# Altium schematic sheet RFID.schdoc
size 297 x 209 mm; Symbol: Drawing-Symbol_A4; @Project Name: Hưhwwuey; @Page Count: 10; @Update Date: 2026-10-23; @Create Date: 2026-10-23; @Schematic Name: Schematic1; @Page No: 10; @Page Name: P1; Company: EasyEDA.com; Version: V1.0; Page Size: A4; Device: Drawing-Symbol_A4; @Create Time: 15:50:34; @Update Time: 15:50:34; Border: 1; Width: 1170; Height: 825; Region Start: 1; X Region Count: 6; Y Region Count: 4; Blade Width: 10; Title Block Position: 3; @Board Name: Board1
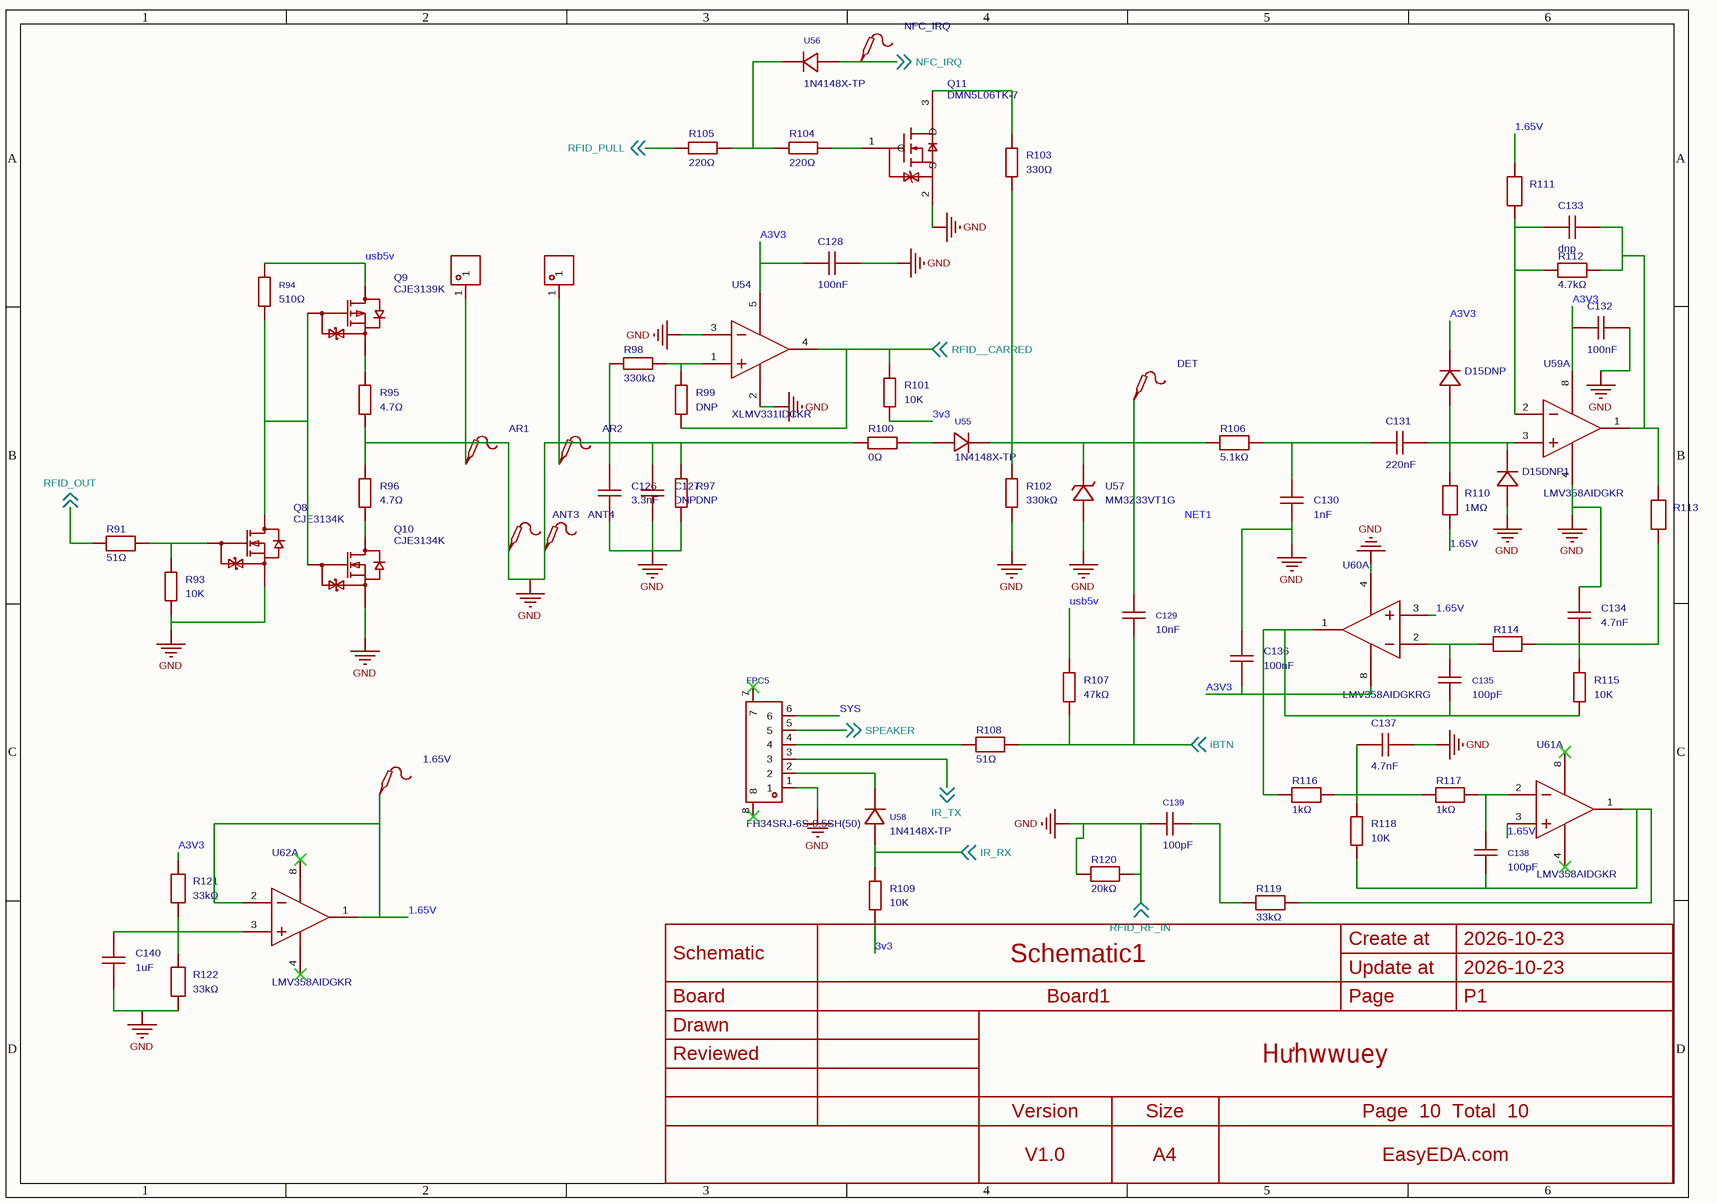
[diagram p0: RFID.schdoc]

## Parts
C126  3.3nF  [C0805]
C127  DNP  [C0402]
C128  100nF  [C0402]
C129  10nF  [C0402]
C130  1nF  [C0402]
C131  220nF  [C1206]
C132  100nF  [C0402]
C133  dnp  [C0402]
C134  4.7nF  [C0402]
C135  100pF  [C0402]
C136  100nF  [C0402]
C137  4.7nF  [C0402]
C138  100pF  [C0402]
C139  100pF  [C0402]
C140  1uF  [C0402]
CN6  YTC1P-3515-M20  [CONN-SMD_YTC1P-3515-M20]  (value not drawn)
CN7  YTC1P-3515-M20  [CONN-SMD_YTC1P-3515-M20]  (value not drawn)
D15DNP  (no value)  [DO-41_BD2.4-L4.7-P8.70-D0.9-RD]
D15DNP1  (no value)  [DO-41_BD2.4-L4.7-P8.70-D0.9-RD]
FPC5  FH34SRJ-6S-0.5SH(50)  [FFC-SMD_6P-P0.50_FH34SRJ-6S-0.5SH]
Q8  CJE3134K  [SOT-523-3_L1.6-W0.8-P1.00-LS1.6-BR]
Q9  CJE3139K  [SC-75-3_L1.6-W0.8-P1.00-LS1.7-BR]
Q10  CJE3134K  [SOT-523-3_L1.6-W0.8-P1.00-LS1.6-BR]
Q11  DMN5L06TK-7  [SOT-523-3_L1.6-W0.8-P1.00-LS1.6-BR]
R91  51Ω  [R0402]
R93  10K  [R0402]
R94  510Ω  [R0402]
R95  4.7Ω  [R0402]
R96  4.7Ω  [R0402]
R97  DNP  [R0402]
R98  330kΩ  [R0402]
R99  DNP  [R0402]
R100  0Ω  [R0402]
R101  10K  [R0402]
R102  330kΩ  [R0402]
R103  330Ω  [R0402]
R104  220Ω  [R0402]
R105  220Ω  [R0402]
R106  5.1kΩ  [R0402]
R107  47kΩ  [R0402]
R108  51Ω  [R0402]
R109  10K  [R0402]
R110  1MΩ  [R0402]
R111  (no value)  [R0402]
R112  4.7kΩ  [R0402]
R113  (no value)  [R0402]
R114  (no value)  [R0402]
R115  10K  [R0402]
R116  1kΩ  [R0402]
R117  1kΩ  [R0402]
R118  10K  [R0402]
R119  33kΩ  [R0402]
R120  20kΩ  [R0402]
R121  33kΩ  [R0402]
R122  33kΩ  [R0402]
TP58  AR1  [Test-Point-0.5mm]
TP59  ANT3  [Test-Point-0.5mm]
TP60  ANT4  [Test-Point-0.5mm]
TP61  AR2  [Test-Point-0.5mm]
TP62  NFC_IRQ  [Test-Point-0.5mm]
TP63  DET  [Test-Point-0.5mm]
TP64  1.65V  [Test-Point-0.5mm]
U54  XLMV331IDCKR  [SC-70-5_L2.1-W1.3-P0.65-LS2.1-BR]
U55  1N4148X-TP  [SOD-523F_L1.2-W0.8-LS1.7-RD]
U56  1N4148X-TP  [SOD-523F_L1.2-W0.8-LS1.7-RD]
U57  MM3Z33VT1G  [SOD-323_L1.7-W1.3-LS2.5-RD]
U58  1N4148X-TP  [SOD-523F_L1.2-W0.8-LS1.7-RD]
U59  LMV358AIDGKR  [VSSOP-8_L3.0-W3.0-P0.65-LS5.0-BL]  (part A of 2)
U60  LMV358AIDGKRG  [MSOP-8_L3.0-W3.0-P0.65-LS4.9-BL]  (part A of 2)
U61  LMV358AIDGKR  [VSSOP-8_L3.0-W3.0-P0.65-LS5.0-BL]  (part A of 2)
U62  LMV358AIDGKR  [VSSOP-8_L3.0-W3.0-P0.65-LS5.0-BL]  (part A of 2)

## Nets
GND: C126.1 C126.2 C127.1 C127.2 C128.1 C130.1 C132.1 C134.2 C136.1 C137.1 C139.2 C140.1 CN6.1 CN7.1 D15DNP1.2(A) FPC5.1 Q8.2(S) Q10.2(S) Q11.2(S) R93.1 R95.1 R96.2 R97.1 R97.2 R98.1 R100.1 R102.1 R120.1 R120.2 R122.1 TP58.1 TP59.1 TP60.1 TP61.1 U54.2(V-) U54.3(-IN) U57.2(A) U59.4(V-) U60.4(V-) ; off-sheet RFID_RF_IN  [also labelled RFID_RF_IN]
1.65V: R110.1 R111.2 TP64.1 U60.3(+IN_A) U61.3(+INA) U62.1(OUTA) U62.2(-INA)
3v3: R101.1 R109.1
A3V3: C128.2 C132.2 C136.2 D15DNP.1(K) R121.2 U54.5(V+) U59.8(V+) U60.8(V+)
iBTN: C129.1 R107.1 R108.2 ; off-sheet iBTN
IR_RX: R109.2 U58.2(A) ; off-sheet IR_RX
IR_TX: FPC5.3 ; off-sheet IR_TX
NFC_IRQ: TP62.1 U56.2(A) ; off-sheet NFC_IRQ
RFID__CARRED: R99.1 R101.2 U54.4(OUT) ; off-sheet RFID__CARRED
RFID_OUT: R91.1 ; off-sheet RFID_OUT
RFID_PULL: R105.1 ; off-sheet RFID_PULL
SPEAKER: FPC5.5 ; off-sheet SPEAKER
SYS: FPC5.6
usb5v: Q9.3(D) R94.2 R107.2
NetC129_2: C129.2 R102.2 R103.1 R106.1 TP63.1 U55.1(C) U57.1(C)
NetC130_2: C130.2 C131.1 R106.2
NetC131_2: C131.2 D15DNP.2(A) D15DNP1.1(K) R110.2 U59.3(+INA)
NetC133_1: C133.1 R112.2 R113.2 U59.1(OUTA)
NetC133_2: C133.2 R111.1 R112.1 U59.2(-INA)
NetC134_1: C134.1 R113.1 R114.1 R115.2
NetC135_1: C135.1 R115.1 R116.1 U60.1(OUT_A)
NetC135_2: C135.2 R114.2 U60.2(-IN_A)
NetC137_2: C137.2 R116.2 R117.1 R118.2
NetC138_1: C138.1 R118.1 R119.2 U61.1(OUTA)
NetC138_2: C138.2 R117.2 U61.2(-INA)
NetC139_1: C139.1 R119.1
NetC140_2: C140.2 R121.1 R122.2 U62.3(+INA)
NetFPC5_2: FPC5.2 U58.1(C)
NetFPC5_4: FPC5.4 R108.1
NetQ8_1: Q8.1(G) R91.2 R93.2
NetQ8_3: Q8.3(D) Q9.1(G) Q10.1(G) R94.1
NetQ9_2: Q9.2(S) R95.2
NetQ10_3: Q10.3(D) R96.1
NetQ11_1: Q11.1(G) R104.2
NetQ11_3: Q11.3(D) R103.2
NetR98_2: R98.2 R99.2 U54.1(+IN)
NetR100_2: R100.2 U55.2(A)
NetR104_1: R104.1 R105.2 U56.1(C)

Not connected (* = marked no-connect by the designer): FPC5 7* 8*; U61 4(V-)* 8(V+)*; U62 4(V-)* 8(V+)*

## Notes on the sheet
- Labels drawn without touching a wire or pin: NET1

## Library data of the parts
C126 = 0805N332J101CT: Capacitance:3.3nF Tolerance:±5% Tolerance:±5% Voltage Rating:100V Temperature Coefficient:NP0; Manufacturer: Walsin(华新科); AddInBom: yes; ModelId: 8c88e81f49c6409b980720ec8953afb60819f05c4eef4c71ace90d822a990e87; ModelName: C0805_L2.0-W1.3-H1.3; ModelTransform: 78.74,51.181,0,0,0,0,0,0.0005,0; Tolerance: ±5%; Voltage Rating: 100V; Temperature Coefficient: NP0
C127 C133 = CAP_0402: Symbol: CAP_OLD; 3D Model: b7d13df3e9464d7a99d0651d1a5b4d570819f05c4eef4c71ace90d822a990e87; 3D Model Transform: 39.37,19.685,0,0,0,0,0,0,0; Add into BOM: no; ConvertToPcb: yes; ModelName: C0402_L1.0-W0.5-H0.5
C128 C132 C136 = CAP_0402: Symbol: CAP_OLD; 3D Model: b7d13df3e9464d7a99d0651d1a5b4d570819f05c4eef4c71ace90d822a990e87; 3D Model Transform: 39.37,19.685,0,0,0,0,0,0,0; ConvertToPcb: yes; ModelName: C0402_L1.0-W0.5-H0.5
C129 = CC0402KRX7R9BB103: Capacitance:10nF Tolerance:±10% Tolerance:±10% Voltage Rating:50V Temperature Coefficient:X7R; Manufacturer: YAGEO(国巨); 3D Model: b7d13df3e9464d7a99d0651d1a5b4d570819f05c4eef4c71ace90d822a990e87; 3D Model Transform: 39.37,19.685,0,0,0,0,0,0,0; Tolerance: ±10%; Voltage Rating: 50V; Temperature Coefficient: X7R; AddInBom: yes; ModelName: C0402_L1.0-W0.5-H0.5
C130 = 0402CG102J500NT: Capacitance:1nF Tolerance:±5% Tolerance:±5% Voltage Rating:50V Temperature Coefficient:C0G; Manufacturer: FH(风华); AddInBom: yes; ModelId: b7d13df3e9464d7a99d0651d1a5b4d570819f05c4eef4c71ace90d822a990e87; ModelName: C0402_L1.0-W0.5-H0.5; ModelTransform: 39.37,19.685,0,0,0,0,0,0,0; Tolerance: ±5%; Voltage Rating: 50V; Temperature Coefficient: C0G
C131 = 1206B224K500CT: Capacitance:220nF Tolerance:±10% Tolerance:±10% Voltage Rating:50V Temperature Coefficient:X7R; Manufacturer: Walsin(华新科); AddInBom: yes; ModelId: c6790e9475e1483991d2c64340b24e960819f05c4eef4c71ace90d822a990e87; ModelName: C1206_L3.2-W1.6-H1.3; ModelTransform: 125.984,62.992,0,0,0,0,0,0,0; Tolerance: ±10%; Voltage Rating: 50V; Temperature Coefficient: X7R
C134 C137 = 0402B472J500CT: Capacitance:4.7nF Tolerance:±5% Tolerance:±5% Voltage Rating:50V Temperature Coefficient:X7R; Manufacturer: Walsin(华新科); AddInBom: yes; ModelId: b7d13df3e9464d7a99d0651d1a5b4d570819f05c4eef4c71ace90d822a990e87; ModelName: C0402_L1.0-W0.5-H0.5; ModelTransform: 39.37,19.685,0,0,0,0,0,0,0; Tolerance: ±5%; Voltage Rating: 50V; Temperature Coefficient: X7R
C135 C138 C139 = CC0402JRNPO9BN101: Capacitance:100pF Tolerance:±5% Tolerance:±5% Voltage Rating:50V Temperature Coefficient:NP0; Manufacturer: YAGEO(国巨); AddInBom: yes; ModelId: b7d13df3e9464d7a99d0651d1a5b4d570819f05c4eef4c71ace90d822a990e87; ModelName: C0402_L1.0-W0.5-H0.5; ModelTransform: 39.37,19.685,0,0,0,0,0,0,0; Tolerance: ±5%; Voltage Rating: 50V; Temperature Coefficient: NP0
C140 = 0402X105K160CT: Capacitance:1uF Tolerance:±10% Tolerance:±10% Voltage Rating:16V Temperature Coefficient:X5R; Manufacturer: Walsin(华新科); AddInBom: yes; ModelId: b7d13df3e9464d7a99d0651d1a5b4d570819f05c4eef4c71ace90d822a990e87; ModelName: C0402_L1.0-W0.5-H0.5; ModelTransform: 39.37,19.685,0,0,0,0,0,0,0; Tolerance: ±10%; Voltage Rating: 16V; Temperature Coefficient: X5R
CN6 CN7 = YTC1P-3515-M20: Type:Pogo Pin Number of Pins:1P Overall Length/Height:4mm Contact Material:Brass Contact Plating:Gold; Manufacturer: YIYUAN(怡远); 3D Model: e956e29c821d4094900f1c4d8f713bf40819f05c4eef4c71ace90d822a990e87; 3D Model Transform: 78.624,78.682,0,0,0,0,0,0,0; Overall Length/Height: 4mm; AddInBom: yes
D15DNP D15DNP1 = 1N4007: Symbol: D_1N4007; Add into BOM: no; ConvertToPcb: yes; ModelId: 39d8e4572d564e62a86d2224fc908dd80819f05c4eef4c71ace90d822a990e87; ModelName: DO-41_D2.4-L4.7-P8.70; ModelTransform: 374.016,94.488,0,0,0,0,0,0,-137.795
FPC5 = FH34SRJ-6S-0.5SH(50): Locking Feature:Flip-top (front insert,rear flip) Contact Type:Double-Sided Contacts, Top and Bottom Entry Number of Contacts:6P Pitch:0.5mm Mounting Type:Surface Mount, Right Angle FFC, FCB Thickness:0.3mm FFC, FCB Thickness:0.3mm Height Above Board:1mm; Manufacturer: HRS(广濑); AddInBom: yes; ModelId: 1b1aec8cff634776880d16aaa310328b0819f05c4eef4c71ace90d822a990e87; ModelName: FFC-SMD_P0.50-WS-6P; ModelTransform: 196.85,125.984,0,0,0,0,0,0.002,0; Number of Contacts: 6P; Pitch: 0.5mm; FFC, FCB Thickness: 0.3mm; Rated Voltage (Max): 50V; Current Rating (Max): 500mA; FPC/FFC Lock: Without buckle; Forward Foot / Back Foot: No polarity
Q8 Q10 = CJE3134K: Number:1 N-channel Drain to Source Voltage:20V Current - Continuous Drain(Id):750mA RDS(on):380mΩ@4.5V Pd - Power Dissipation:150mW Gate Threshold Voltage (Vgs(th)):350mV Gate Charge(Qg):- Input Capacitance(Ciss):120pF Reverse Transfer Capacitance (Crss@V; Manufacturer: CJ(江苏长电/长晶); AddInBom: yes; ModelId: 1cc59aa5ffe4420193f3c1f87584e8b70819f05c4eef4c71ace90d822a990e87; ModelName: SOT-523-3P_L1.6-W0.8-H0.9-LS1.6-P0.50; ModelTransform: 63.48633,62.992,0,180,0,0,0,0,0; Drain to Source Voltage: 20V; Current - Continuous Drain(Id): 750mA; Pd - Power Dissipation: 150mW; Gate Threshold Voltage (Vgs(th)): 350mV; Input Capacitance(Ciss): 120pF; Reverse Transfer Capacitance (Crss@Vds): 15pF; Output Capacitance(Coss): 20pF; Vgs: ±12V
Q9 = CJE3139K: Number:1 P-Channel Drain to Source Voltage:20V Current - Continuous Drain(Id):660mA RDS(on):520mΩ@4.5V Pd - Power Dissipation:150mW Gate Threshold Voltage (Vgs(th)):350mV Gate Charge(Qg):- Input Capacitance(Ciss):170pF Reverse Transfer Capacitance (Crss@V; Manufacturer: CJ(江苏长电/长晶); AddInBom: yes; ModelId: f2b5cdcfb1524051bb2c314de36aeac10819f05c4eef4c71ace90d822a990e87; ModelName: SC-75-3_L1.6-W0.8-H0.9-LS1.6-P1.0; ModelTransform: 63.48633,62.992,0,180,0,0,0,0.005,0; Drain to Source Voltage: 20V; Current - Continuous Drain(Id): 660mA; Pd - Power Dissipation: 150mW; Gate Threshold Voltage (Vgs(th)): 350mV; Input Capacitance(Ciss): 170pF; Reverse Transfer Capacitance (Crss@Vds): 15pF; Vgs: ±12V
Q11 = DMN5L06TK-7: Number:1 N-channel Drain to Source Voltage:50V Current - Continuous Drain(Id):280mA RDS(on):2.5Ω@2.5V Pd - Power Dissipation:150mW Gate Threshold Voltage (Vgs(th)):3V Gate Charge(Qg):- Input Capacitance(Ciss):50pF Reverse Transfer Capacitance (Crss@Vds):5; Manufacturer: DIODES(美台); AddInBom: yes; ModelId: 1cc59aa5ffe4420193f3c1f87584e8b70819f05c4eef4c71ace90d822a990e87; ModelName: SOT-523-3P_L1.6-W0.8-H0.9-LS1.6-P0.50; ModelTransform: 63.48633,62.992,0,180,0,0,0,0,0; Drain to Source Voltage: 50V; Current - Continuous Drain(Id): 280mA; Pd - Power Dissipation: 150mW; Gate Threshold Voltage (Vgs(th)): 3V; Input Capacitance(Ciss): 50pF; Reverse Transfer Capacitance (Crss@Vds): 5pF; Output Capacitance(Coss): 25pF; Vgs: ±20V
R91 R108 = WR04X510JTL_C384323: Type:Thick Film Resistors Resistance: Tolerance:±5% Tolerance:±5% Power(Watts): Overload Voltage (Max): Temperature Coefficient:±100ppm/℃ Temperature Coefficient:±100ppm/℃ Operating Temperature Range:-55℃~+155℃ Operating Temperature Range:-55℃~+155℃; Manufacturer: Walsin(华新科); AddInBom: yes; ModelId: efdecb7dae4442949d28eecaf748420f0819f05c4eef4c71ace90d822a990e87; ModelName: R0402_L1.0-W0.5-H0.4; ModelTransform: 39.37,19.685,0,0,0,0,0,0,0; Tolerance: ±5%
R93 R101 R109 R115 R118 = Res_0402: Symbol: Res; 3D Model: efdecb7dae4442949d28eecaf748420f0819f05c4eef4c71ace90d822a990e87; 3D Model Transform: 39.37,19.685,0,0,0,0,0,0,0; ConvertToPcb: yes; ModelName: R0402_L1.0-W0.5-H0.4
R94 = RTT02511JTH: Type:Thick Film Resistor Resistance:510Ω Tolerance:±5% Tolerance:±5% Power(Watts):62.5mW Voltage-Supply(Max):50V Temperature Coefficient:±100ppm/℃ Temperature Coefficient:±100ppm/℃ Operating Temperature:-55℃~+155℃ Operating Temperature:-55℃~+155℃; Manufacturer: RALEC(旺诠); 3D Model: efdecb7dae4442949d28eecaf748420f0819f05c4eef4c71ace90d822a990e87; 3D Model Transform: 39.37,19.685,0,0,0,0,0,0,0; Tolerance: ±5%; Power(Watts): 62.5mW; Voltage-Supply(Max): 50V; AddInBom: yes; ModelName: R0402_L1.0-W0.5-H0.4
R95 R96 = WR04X4R7JTL: Type:Thick Film Resistor Resistance:4.7Ω Tolerance:±5% Tolerance:±5% Power(Watts):62.5mW Voltage-Supply(Max):50V Temperature Coefficient:-200ppm/℃~+400ppm/℃ Temperature Coefficient:-200ppm/℃~+400ppm/℃ Operating Temperature:-55℃~+155℃ Operating Temperature; Manufacturer: Walsin(华新科); AddInBom: yes; ModelId: efdecb7dae4442949d28eecaf748420f0819f05c4eef4c71ace90d822a990e87; ModelName: R0402_L1.0-W0.5-H0.4; ModelTransform: 39.37,19.685,0,0,0,0,0,0,0; Tolerance: ±5%; Power(Watts): 62.5mW; Voltage-Supply(Max): 50V
R97 R99 = Res_0402: Symbol: Res; 3D Model: efdecb7dae4442949d28eecaf748420f0819f05c4eef4c71ace90d822a990e87; 3D Model Transform: 39.37,19.685,0,0,0,0,0,0,0; Add into BOM: no; ConvertToPcb: yes; ModelName: R0402_L1.0-W0.5-H0.4
R98 R102 = WR04X3303FTL: Type:Thick Film Resistors Resistance: Tolerance:±1% Tolerance:±1% Power(Watts): Overload Voltage (Max): Temperature Coefficient:±100ppm/℃ Temperature Coefficient:±100ppm/℃ Operating Temperature Range:-55℃~+155℃ Operating Temperature Range:-55℃~+155℃; Manufacturer: Walsin(华新科); AddInBom: yes; ModelId: efdecb7dae4442949d28eecaf748420f0819f05c4eef4c71ace90d822a990e87; ModelName: R0402_L1.0-W0.5-H0.4; ModelTransform: 39.37,19.685,0,0,0,0,0,0,0; Tolerance: ±1%
R100 = WR04X000PTL: Type:Thick Film Resistor Resistance:0Ω Tolerance:- Tolerance:- Power(Watts):62.5mW Voltage-Supply(Max):50V Temperature Coefficient:-200ppm/℃~+400ppm/℃ Temperature Coefficient:-200ppm/℃~+400ppm/℃ Operating Temperature:-55℃~+155℃ Operating Temperature:-55℃~; Manufacturer: Walsin(华新科); 3D Model: efdecb7dae4442949d28eecaf748420f0819f05c4eef4c71ace90d822a990e87; 3D Model Transform: 39.37,19.685,0,0,0,0,0,0,0; Power(Watts): 62.5mW; Voltage-Supply(Max): 50V; AddInBom: yes; ModelName: R0402_L1.0-W0.5-H0.4
R103 = WR04X331JTL: Type:Thick Film Resistor Resistance:330Ω Tolerance:±5% Tolerance:±5% Power(Watts):62.5mW Voltage-Supply(Max):50V Temperature Coefficient:±100ppm/℃ Temperature Coefficient:±100ppm/℃ Operating Temperature:-55℃~+155℃ Operating Temperature:-55℃~+155℃; Manufacturer: Walsin(华新科); 3D Model: efdecb7dae4442949d28eecaf748420f0819f05c4eef4c71ace90d822a990e87; 3D Model Transform: 39.37,19.685,0,0,0,0,0,0,0; Tolerance: ±5%; Power(Watts): 62.5mW; Voltage-Supply(Max): 50V; AddInBom: yes; ModelName: R0402_L1.0-W0.5-H0.4
R104 R105 = WR04X221JTL: Type:Thick Film Resistors Resistance: Tolerance:±5% Tolerance:±5% Power(Watts): Overload Voltage (Max): Temperature Coefficient:±100ppm/℃ Temperature Coefficient:±100ppm/℃ Operating Temperature Range:-55℃~+155℃ Operating Temperature Range:-55℃~+155℃; Manufacturer: Walsin(华新科); AddInBom: yes; ModelId: efdecb7dae4442949d28eecaf748420f0819f05c4eef4c71ace90d822a990e87; ModelName: R0402_L1.0-W0.5-H0.4; ModelTransform: 39.37,19.685,0,0,0,0,0,0,0; Tolerance: ±5%
R106 = WR04X512JTL_C384321: Type:Thick Film Resistor Resistance:5.1kΩ Tolerance:±5% Tolerance:±5% Power(Watts):62.5mW Voltage-Supply(Max):50V Temperature Coefficient:±100ppm/℃ Temperature Coefficient:±100ppm/℃ Operating Temperature:-55℃~+155℃ Operating Temperature:-55℃~+155℃; Manufacturer: Walsin(华新科); AddInBom: yes; ModelId: efdecb7dae4442949d28eecaf748420f0819f05c4eef4c71ace90d822a990e87; ModelName: R0402_L1.0-W0.5-H0.4; ModelTransform: 39.37,19.685,0,0,0,0,0,0,0; Tolerance: ±5%; Power(Watts): 62.5mW; Voltage-Supply(Max): 50V
R107 = RC0402JR-0747KL: Type:Thick Film Resistors Resistance: Tolerance:±5% Tolerance:±5% Power(Watts): Overload Voltage (Max): Temperature Coefficient:±100ppm/℃ Temperature Coefficient:±100ppm/℃ Operating Temperature Range:-55℃~+155℃ Operating Temperature Range:-55℃~+155℃; Manufacturer: YAGEO(国巨); AddInBom: yes; ModelId: efdecb7dae4442949d28eecaf748420f0819f05c4eef4c71ace90d822a990e87; ModelName: R0402_L1.0-W0.5-H0.4; ModelTransform: 39.37,19.685,0,0,0,0,0,0,0; Tolerance: ±5%
R110 = WR04X105JTL_C384387: Type:Thick Film Resistor Resistance:1MΩ Tolerance:±5% Tolerance:±5% Power(Watts):62.5mW Voltage-Supply(Max):50V Temperature Coefficient:±100ppm/℃ Temperature Coefficient:±100ppm/℃ Operating Temperature:-55℃~+155℃ Operating Temperature:-55℃~+155℃; Manufacturer: Walsin(华新科); AddInBom: yes; ModelId: efdecb7dae4442949d28eecaf748420f0819f05c4eef4c71ace90d822a990e87; ModelName: R0402_L1.0-W0.5-H0.4; ModelTransform: 39.37,19.685,0,0,0,0,0,0,0; Tolerance: ±5%; Power(Watts): 62.5mW; Voltage-Supply(Max): 50V
R111 R113 = WR04X102JTL: 功率:1/16W;精度:±5%;温度系数:±100ppm/℃;阻值:1kΩ;最大工作电压:50V;工作温度范围:-55℃~+155℃;; Manufacturer: Walsin(华新科); AddInBom: yes; ModelId: 671aefced39d4c318694bba8bd8efd39419e2bde8089452eaf6035c271c14a6f; ModelName: R0402_L1.0-W0.5-H0.5; ModelTransform: 39.37,19.685,0,0,0,0,0,0.0005,0; Power(Watts): 1/16W; Tolerance: ±5%; Value: 1kΩ; Overload Voltage (Max): 50V
R112 = WR04X472JTL: 电阻类型:厚膜电阻;阻值:4.7kΩ;精度:±5%;功率:62.5mW;工作电压:50V;温度系数:±100ppm/℃;; Manufacturer: Walsin(华新科); AddInBom: yes; ModelId: 98c88bc2b9094f218f3a3e30a70127380819f05c4eef4c71ace90d822a990e87; ModelName: R0402_L1.0-W0.5-H0.4; ModelTransform: 39.37,19.685,0,0,0,0,0,0,0; Tolerance: ±5%; Power(Watts): 62.5mW; Voltage-Supply(Max): 50V
R114 = WR04X102JTL: 功率:1/16W;精度:±5%;温度系数:±100ppm/℃;阻值:1kΩ;最大工作电压:50V;工作温度范围:-55℃~+155℃;; Manufacturer: Walsin(华新科); 3D Model: 671aefced39d4c318694bba8bd8efd39419e2bde8089452eaf6035c271c14a6f; 3D Model Transform: 39.37,19.685,0,0,0,0,0,0.0005,0; Power(Watts): 1/16W; Tolerance: ±5%; Value: 1kΩ; Overload Voltage (Max): 50V; AddInBom: yes; ModelName: R0402_L1.0-W0.5-H0.5
R116 R117 = WR04X102JTL_C384390: Type:Thick Film Resistor Resistance:1kΩ Tolerance:±5% Tolerance:±5% Power(Watts):62.5mW Voltage-Supply(Max):50V Temperature Coefficient:±100ppm/℃ Temperature Coefficient:±100ppm/℃ Operating Temperature:-55℃~+155℃ Operating Temperature:-55℃~+155℃; Manufacturer: Walsin(华新科); AddInBom: yes; ModelId: efdecb7dae4442949d28eecaf748420f0819f05c4eef4c71ace90d822a990e87; ModelName: R0402_L1.0-W0.5-H0.4; ModelTransform: 39.37,19.685,0,0,0,0,0,0,0; Tolerance: ±5%; Power(Watts): 62.5mW; Voltage-Supply(Max): 50V
R119 R121 R122 = WR04X333JTL_C384337: Type:Thick Film Resistors Resistance: Tolerance:±5% Tolerance:±5% Power(Watts): Overload Voltage (Max): Temperature Coefficient:±100ppm/℃ Temperature Coefficient:±100ppm/℃ Operating Temperature Range:-55℃~+155℃ Operating Temperature Range:-55℃~+155℃; Manufacturer: Walsin(华新科); AddInBom: yes; ModelId: efdecb7dae4442949d28eecaf748420f0819f05c4eef4c71ace90d822a990e87; ModelName: R0402_L1.0-W0.5-H0.4; ModelTransform: 39.37,19.685,0,0,0,0,0,0,0; Tolerance: ±5%
R120 = WR04X203JTL_C384364: Type:Thick Film Resistor Resistance:20kΩ Tolerance:±5% Tolerance:±5% Power(Watts):62.5mW Voltage-Supply(Max):50V Temperature Coefficient:±100ppm/℃ Temperature Coefficient:±100ppm/℃ Operating Temperature:-55℃~+155℃ Operating Temperature:-55℃~+155℃; Manufacturer: Walsin(华新科); AddInBom: yes; ModelId: efdecb7dae4442949d28eecaf748420f0819f05c4eef4c71ace90d822a990e87; ModelName: R0402_L1.0-W0.5-H0.4; ModelTransform: 39.37,19.685,0,0,0,0,0,0,0; Tolerance: ±5%; Power(Watts): 62.5mW; Voltage-Supply(Max): 50V
TP58-TP64 = Test-Point: Test Point 测试点; AddInBom: yes
U54 = XLMV331IDCKR: Number of Channels:1 Vos - Input Offset Voltage:1mV Ib - Input Bias Current:5pA Propagation Delay Time:100ns Input Hysteresis Voltage (Vhys):3mV Common Mode Rejection Ratio(CMRR):78dB Output Type:Open-drain Output Mode:- Rail to Rail:Rail-to-rail input Qu; Manufacturer: XBLW(芯伯乐); AddInBom: yes; ModelId: 770240de28f449f5b9c3c8a96a0507690819f05c4eef4c71ace90d822a990e87; ModelName: SC-70-5_L2.1-W1.3-H1.0-LS2.1-P0.65; ModelTransform: 82.677,78.74,0,180,0,0,0,0,0; Number of Channels: 1; Vos - Input Offset Voltage: 1mV; Ib - Input Bias Current: 5pA; Propagation Delay Time: 100ns; Input Hysteresis Voltage (Vhys): 3mV; Common Mode Rejection Ratio(CMRR): 78dB; Quiescent Current: 32uA; Single Supply: 1.8V~5.5V; Input Offset Voltage Drift(Vos TC): 2uV/℃; Input Offset Current(Ios): 10pA
U55 U56 U58 = 1N4148X-TP: Diode Configuration:1 Independent Pd - Power Dissipation:200mW Current - Rectified:150mA Voltage - DC Reverse(Vr):75V Voltage - Forward(Vf@If):1.25V@150mA Non-Repetitive Peak Forward Surge Current:2A Reverse Leakage Current (Ir):1uA@75V Reverse Recovery T; Manufacturer: MCC(美微科); 3D Model: 53f385f253c24b16903baed56d7fb4c80819f05c4eef4c71ace90d822a990e87; 3D Model Transform: 62.992,31.496,0,0,0,0,-0.005,0.16,0; Pd - Power Dissipation: 200mW; Current - Rectified: 150mA; Voltage - DC Reverse(Vr): 75V; Non-Repetitive Peak Forward Surge Current: 2A; Reverse Recovery Time (trr): 4ns; Operating Junction Temperature Range: -65℃~+150℃; AddInBom: yes; ModelName: SOD-523F_L1.2-W0.8-H0.6-LS1.6
U57 = MM3Z33VT1G: Diode Configuration:1 Independent Zener Voltage(Nom):33V Reverse Leakage Current (Ir):50nA@23.2V Zener Voltage(Range):31V~35V Zener Voltage(Range):31V~35V Pd - Power Dissipation:300mW Impedance(Zzt):80Ω Impedance(Zzk):300Ω Operating Junction Temperature R; Manufacturer: onsemi(安森美); AddInBom: yes; ModelId: 6a131d361d25416a8cf2b70c0be37c430819f05c4eef4c71ace90d822a990e87; ModelName: SOD-323_L1.7-W1.3-LS2.5-FD; ModelTransform: 98.425,49.2125,0,0,0,0,0,0,0; Zener Voltage(Nom): 33V; Pd - Power Dissipation: 300mW; Impedance(Zzt): 80Ω; Impedance(Zzk): 300Ω; Operating Junction Temperature Range: -65℃~+150℃
U59 = LMV358AIDGKR: 放大器组数:2;带宽(-3db):-;输入偏置电流(Ib):10pA;增益带宽积(GBP):1MHz;压摆率(SR):1.7V/us;轨到轨:轨到轨;; Manufacturer: TI(德州仪器); Relevance: []; AddInBom: yes; ModelId: fe8ada2663e64b00b932016623def7036c81d4c5b605401dba5844f6591d4566; ModelName: VSSOP-8_L3.0-W3.0-H1.1-LS4.9-P0.65; ModelTransform: 197.34433,118.11,0,90,0,0,0,0.0005,0; Number of Circuits: 2; Current - Input Bias(Ib): 10pA; Gain Bandwidth Product(GBP): 1MHz; Rail to Rail: 轨到轨; Output Current: 40mA
U60 = LMV358AIDGKRG: Number of Channels:2 Rail to Rail:Rail-to-Rail Input, Rail-to-Rail Output Gain Bandwidth Product:1.2MHz Vos - Input Offset Voltage:700uV Input Offset Voltage Drift(Vos TC):1uV/℃ Slew Rate:1V/us Ib - Input Bias Current:5pA Input Offset Current(Ios):10pA In; Manufacturer: HGC(深圳汉芯); Relevance: []; AddInBom: yes; ModelId: 0d61484c2b2f403fbec30fc27e0c9c520819f05c4eef4c71ace90d822a990e87; ModelName: MSOP-8_L3.0-W3.0-H1.1-LS4.9-P0.65; ModelTransform: 118.11,192.913,0,0,0,0,0,0,0; Number of Channels: 2; Gain Bandwidth Product: 1.2MHz; Vos - Input Offset Voltage: 700uV; Input Offset Voltage Drift(Vos TC): 1uV/℃; Slew Rate: 1V/us; Ib - Input Bias Current: 5pA; Input Offset Current(Ios): 10pA; Input Voltage Noise Density: 30nV/√Hz@1kHz; Common Mode Rejection Ratio(CMRR): 83dB; Quiescent Current: 85uA; Output Current: 40mA; Single supply: 1.8V~5.5V; Dual Supply: -2.75V~-900mV；900mV~2.75V
U61 U62 = LMV358AIDGKR: Number of Channels:2 Rail to Rail:Rail-to-rail output Gain Bandwidth Product:1MHz Vos - Input Offset Voltage:1mV Input Offset Voltage Drift(Vos TC):1uV/℃ Slew Rate:76V/us Ib - Input Bias Current:10pA Input Offset Current(Ios):3pA Input Voltage Noise Densi; Manufacturer: TI(德州仪器); Relevance: []; AddInBom: yes; ModelId: 452b2081c2ff4048a25a8c4e897071360819f05c4eef4c71ace90d822a990e87; ModelName: VSSOP-8_L3.0-W3.0-H1.1-LS4.9-P0.65; ModelTransform: 197.34433,118.11,0,90,0,0,0,0.0005,0; Number of Channels: 2; Gain Bandwidth Product: 1MHz; Vos - Input Offset Voltage: 1mV; Input Offset Voltage Drift(Vos TC): 1uV/℃; Slew Rate: 76V/us; Ib - Input Bias Current: 10pA; Input Offset Current(Ios): 3pA; Input Voltage Noise Density: 30nV/√Hz@10kHz; Common Mode Rejection Ratio(CMRR): 96dB; Quiescent Current: 70uA; Output Current: 40mA; Single supply: 2.5V~5.5V; Dual Supply: -2.75V~-1.25V；1.25V~2.75V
